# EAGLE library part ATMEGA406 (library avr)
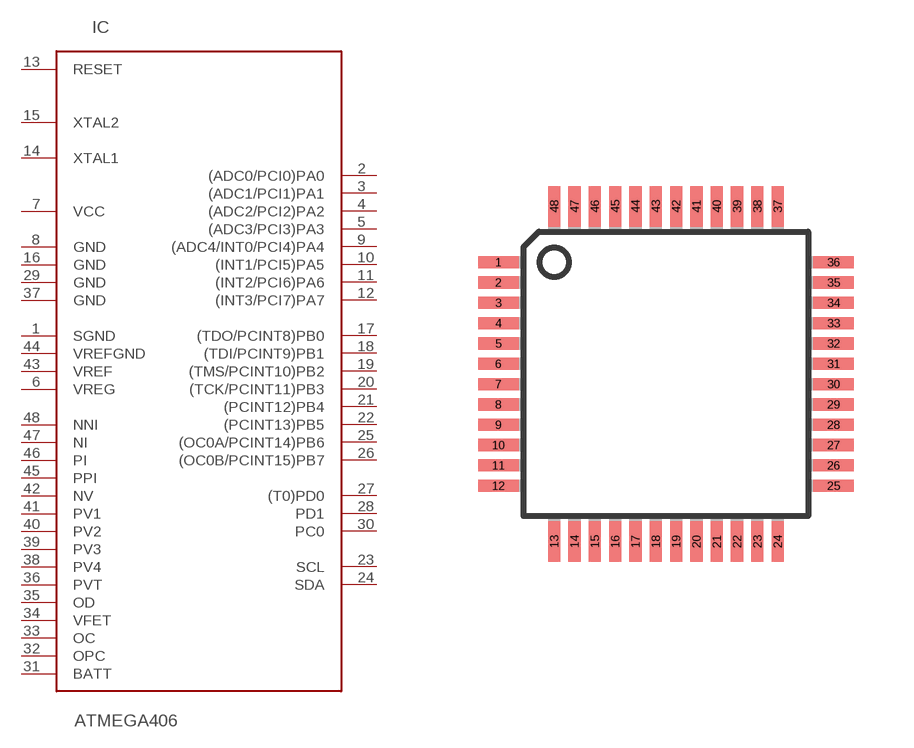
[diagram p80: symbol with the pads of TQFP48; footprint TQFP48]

Designator prefix IC

## ATMEGA406-1AAU  [TQFP48]
1  SGND
2  (ADC0/PCI0)PA0
3  (ADC1/PCI1)PA1
4  (ADC2/PCI2)PA2
5  (ADC3/PCI3)PA3
6  VREG
7  VCC  pwr
8  GND  pwr
9  (ADC4/INT0/PCI4)PA4
10  (INT1/PCI5)PA5
11  (INT2/PCI6)PA6
12  (INT3/PCI7)PA7
13  RESET
14  XTAL1
15  XTAL2
16  GND  pwr
17  (TDO/PCINT8)PB0
18  (TDI/PCINT9)PB1
19  (TMS/PCINT10)PB2
20  (TCK/PCINT11)PB3
21  (PCINT12)PB4
22  (PCINT13)PB5
23  SCL
24  SDA
25  (OC0A/PCINT14)PB6
26  (OC0B/PCINT15)PB7
27  (T0)PD0
28  PD1
29  GND  pwr
30  PC0
31  BATT
32  OPC
33  OC
34  VFET
35  OD
36  PVT
37  GND  pwr
38  PV4
39  PV3
40  PV2
41  PV1
42  NV
43  VREF
44  VREFGND
45  PPI
46  PI
47  NI
48  NNI

## Footprint TQFP48 (pad centres in mm)
Thin Plasic Quad Flat Package
smd 1.016 x 0.305: 1 -4.191,2.794; 2 -4.191,2.286; 3 -4.191,1.778; 4 -4.191,1.27; 5 -4.191,0.762; 6 -4.191,0.254; 7 -4.191,-0.254; 8 -4.191,-0.762; 9 -4.191,-1.27; 10 -4.191,-1.778; 11 -4.191,-2.286; 12 -4.191,-2.794; 25 4.191,-2.794; 26 4.191,-2.286; 27 4.191,-1.778; 28 4.191,-1.27; 29 4.191,-0.762; 30 4.191,-0.254; 31 4.191,0.254; 32 4.191,0.762; 33 4.191,1.27; 34 4.191,1.778; 35 4.191,2.286; 36 4.191,2.794
smd 0.305 x 1.016: 13 -2.794,-4.191; 14 -2.286,-4.191; 15 -1.778,-4.191; 16 -1.27,-4.191; 17 -0.762,-4.191; 18 -0.254,-4.191; 19 0.254,-4.191; 20 0.762,-4.191; 21 1.27,-4.191; 22 1.778,-4.191; 23 2.286,-4.191; 24 2.794,-4.191; 37 2.794,4.191; 38 2.286,4.191; 39 1.778,4.191; 40 1.27,4.191; 41 0.762,4.191; 42 0.254,4.191; 43 -0.254,4.191; 44 -0.762,4.191; 45 -1.27,4.191; 46 -1.778,4.191; 47 -2.286,4.191; 48 -2.794,4.191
